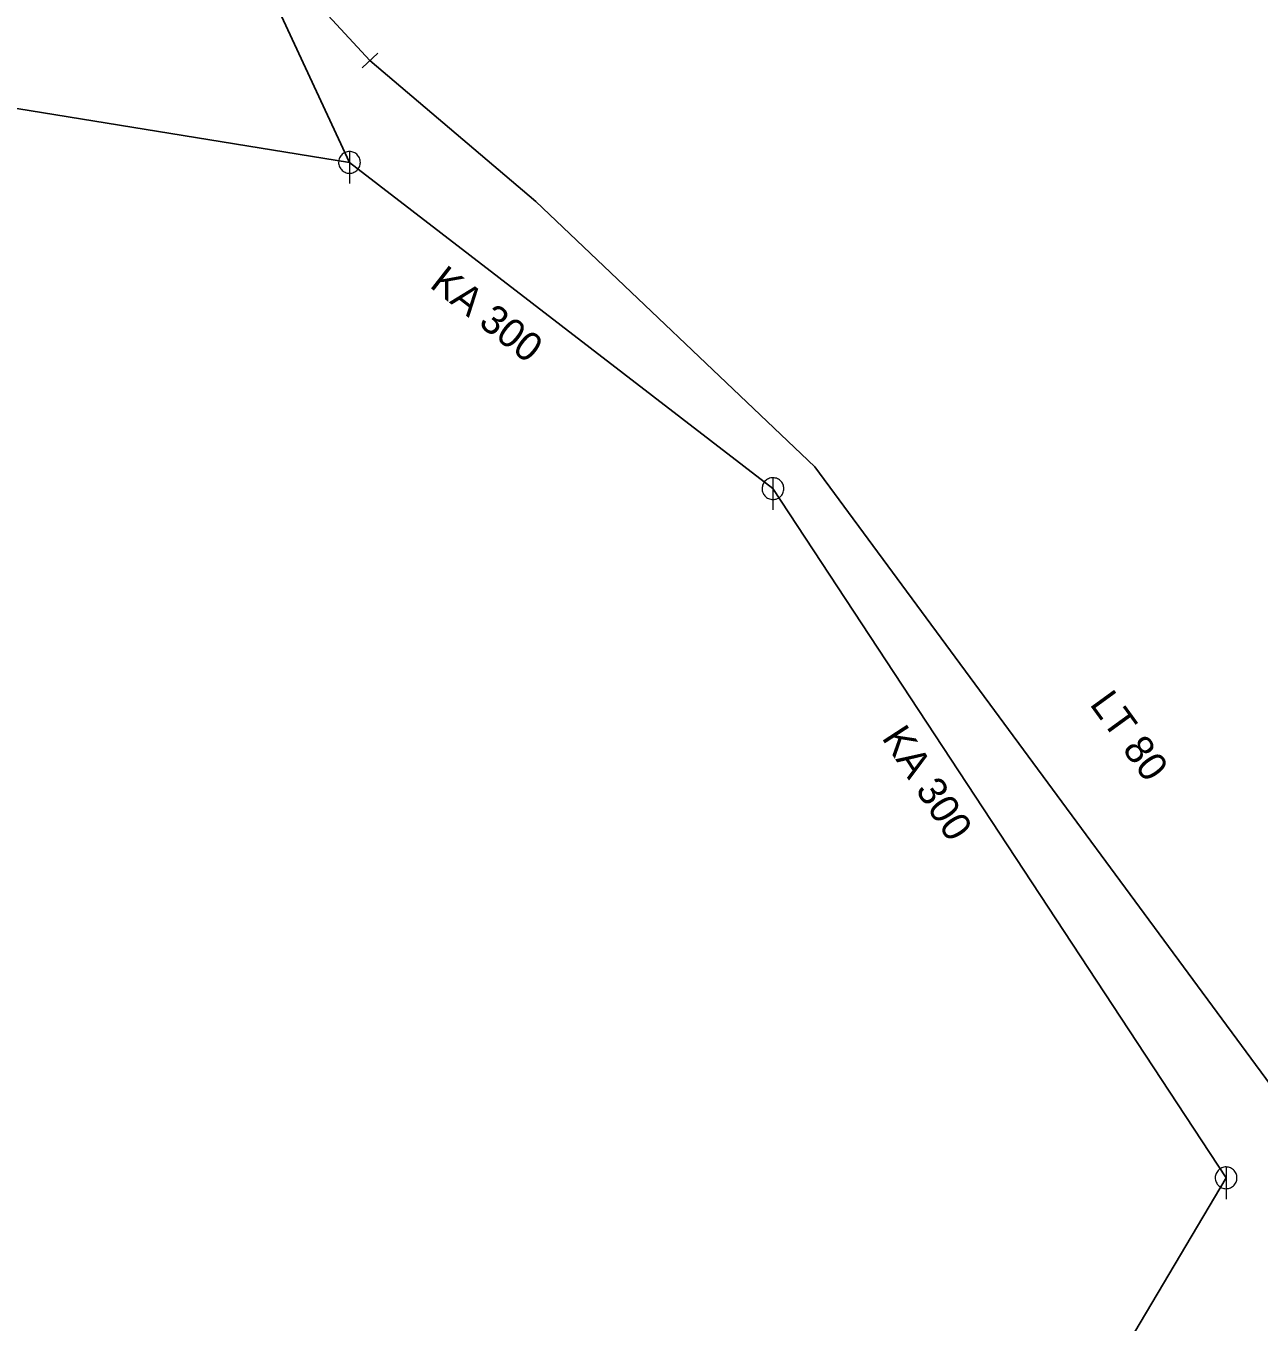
# Model space of a CAD drawing. Extents: x -687515 to -686506, y -974029 to -973461.
# Drawn here: x -687114.54 to -687085.95, y -973866.2 to -973836.14 of the extents above; entities that cross this region are included whole.
import ezdxf
from ezdxf.enums import TextEntityAlignment as Align

# ---------------------------------------------------------------- set-up
doc = ezdxf.new("R2010")
doc.units = 0
doc.header["$LTSCALE"] = 0.27
for name, color, linetype, lineweight in [('1', 7, 'Continuous', 13), ('14', 7, 'Continuous', 25), ('17', 7, 'Continuous', 25), ('22', 7, 'Continuous', 13), ('34', 7, 'Continuous', 13)]:
    doc.layers.add(name, color=color, linetype=linetype, lineweight=lineweight)

msp = doc.modelspace()

# ---------------------------------------------------------------- linework, layer by layer
at = {"layer": '14', "lineweight": 13}
msp.add_line((-687106.566, -973836.941), (-687112.499, -973830.523), dxfattribs=at)
at = {"layer": '14'}
for p, q in [((-687111.064, -973830.634), (-687107.04, -973839.305)), ((-687107.04, -973839.305), (-687097.219, -973846.87)), ((-687097.219, -973846.87), (-687086.71, -973862.85)), ((-687086.71, -973862.85), (-687098.575, -973882.82))]:
    msp.add_line(p, q, dxfattribs=at)
msp.add_lwpolyline([(-687155.19, -973818.55), (-687143.21, -973829.559), (-687133.43, -973835.02), (-687107.04, -973839.305)], dxfattribs=at)
at = {"layer": '17'}
msp.add_lwpolyline([(-687106.566, -973836.941), (-687102.715, -973840.21), (-687096.25, -973846.366), (-687083.209, -973864.046)], dxfattribs=at)
at = {"layer": '22'}
for p, q in [((-687107.039, -973839.053), (-687107.04, -973839.797)), ((-687097.218, -973846.618), (-687097.219, -973847.362)), ((-687086.709, -973862.598), (-687086.71, -973863.342))]:
    msp.add_line(p, q, dxfattribs=at)
for points in [[(-687106.788, -973839.305), (-687106.789, -973839.279), (-687106.793, -973839.253), (-687106.799, -973839.227), (-687106.809, -973839.203), (-687106.821, -973839.179), (-687106.835, -973839.157), (-687106.852, -973839.136), (-687106.87, -973839.118), (-687106.891, -973839.101), (-687106.913, -973839.087), (-687106.937, -973839.075), (-687106.961, -973839.065), (-687106.987, -973839.059), (-687107.013, -973839.055), (-687107.039, -973839.053), (-687107.065, -973839.054), (-687107.091, -973839.058), (-687107.117, -973839.064), (-687107.142, -973839.074), (-687107.165, -973839.086), (-687107.187, -973839.1), (-687107.208, -973839.117), (-687107.226, -973839.135), (-687107.243, -973839.156), (-687107.257, -973839.178), (-687107.269, -973839.202), (-687107.279, -973839.226), (-687107.286, -973839.252), (-687107.29, -973839.278), (-687107.292, -973839.304), (-687107.291, -973839.33), (-687107.287, -973839.356), (-687107.28, -973839.382), (-687107.27, -973839.407), (-687107.258, -973839.43), (-687107.244, -973839.452), (-687107.227, -973839.473), (-687107.209, -973839.491), (-687107.188, -973839.508), (-687107.166, -973839.522), (-687107.143, -973839.534), (-687107.118, -973839.544), (-687107.092, -973839.551), (-687107.066, -973839.555), (-687107.04, -973839.557), (-687107.014, -973839.556), (-687106.988, -973839.552), (-687106.962, -973839.545), (-687106.938, -973839.535), (-687106.914, -973839.523), (-687106.892, -973839.509), (-687106.871, -973839.492), (-687106.853, -973839.474), (-687106.836, -973839.453), (-687106.822, -973839.431), (-687106.81, -973839.408), (-687106.8, -973839.383), (-687106.794, -973839.357), (-687106.79, -973839.331)], [(-687096.967, -973846.87), (-687096.968, -973846.844), (-687096.972, -973846.818), (-687096.978, -973846.792), (-687096.988, -973846.768), (-687097, -973846.744), (-687097.014, -973846.722), (-687097.031, -973846.701), (-687097.049, -973846.683), (-687097.07, -973846.666), (-687097.092, -973846.652), (-687097.116, -973846.64), (-687097.14, -973846.63), (-687097.166, -973846.624), (-687097.192, -973846.62), (-687097.218, -973846.618), (-687097.244, -973846.619), (-687097.27, -973846.623), (-687097.296, -973846.629), (-687097.321, -973846.639), (-687097.344, -973846.651), (-687097.366, -973846.665), (-687097.387, -973846.682), (-687097.405, -973846.7), (-687097.422, -973846.721), (-687097.436, -973846.743), (-687097.448, -973846.767), (-687097.458, -973846.791), (-687097.465, -973846.817), (-687097.469, -973846.843), (-687097.471, -973846.869), (-687097.47, -973846.895), (-687097.466, -973846.921), (-687097.459, -973846.947), (-687097.449, -973846.972), (-687097.437, -973846.995), (-687097.423, -973847.017), (-687097.406, -973847.038), (-687097.388, -973847.056), (-687097.367, -973847.073), (-687097.345, -973847.087), (-687097.322, -973847.099), (-687097.297, -973847.109), (-687097.271, -973847.116), (-687097.245, -973847.12), (-687097.219, -973847.122), (-687097.193, -973847.121), (-687097.167, -973847.117), (-687097.141, -973847.11), (-687097.117, -973847.1), (-687097.093, -973847.088), (-687097.071, -973847.074), (-687097.05, -973847.057), (-687097.032, -973847.039), (-687097.015, -973847.018), (-687097.001, -973846.996), (-687096.989, -973846.973), (-687096.979, -973846.948), (-687096.973, -973846.922), (-687096.969, -973846.896)], [(-687086.458, -973862.85), (-687086.459, -973862.824), (-687086.463, -973862.798), (-687086.469, -973862.772), (-687086.479, -973862.748), (-687086.491, -973862.724), (-687086.505, -973862.702), (-687086.522, -973862.681), (-687086.54, -973862.663), (-687086.561, -973862.646), (-687086.583, -973862.632), (-687086.607, -973862.62), (-687086.631, -973862.61), (-687086.657, -973862.604), (-687086.683, -973862.6), (-687086.709, -973862.598), (-687086.735, -973862.599), (-687086.761, -973862.603), (-687086.787, -973862.609), (-687086.812, -973862.619), (-687086.835, -973862.631), (-687086.857, -973862.645), (-687086.878, -973862.662), (-687086.896, -973862.68), (-687086.913, -973862.701), (-687086.927, -973862.723), (-687086.939, -973862.747), (-687086.949, -973862.771), (-687086.956, -973862.797), (-687086.96, -973862.823), (-687086.962, -973862.849), (-687086.961, -973862.875), (-687086.957, -973862.901), (-687086.95, -973862.927), (-687086.94, -973862.952), (-687086.928, -973862.975), (-687086.914, -973862.997), (-687086.897, -973863.018), (-687086.879, -973863.036), (-687086.858, -973863.053), (-687086.836, -973863.067), (-687086.813, -973863.079), (-687086.788, -973863.089), (-687086.762, -973863.096), (-687086.736, -973863.1), (-687086.71, -973863.102), (-687086.684, -973863.101), (-687086.658, -973863.097), (-687086.632, -973863.09), (-687086.608, -973863.08), (-687086.584, -973863.068), (-687086.562, -973863.054), (-687086.541, -973863.037), (-687086.523, -973863.019), (-687086.506, -973862.998), (-687086.492, -973862.976), (-687086.48, -973862.953), (-687086.47, -973862.928), (-687086.464, -973862.902), (-687086.46, -973862.876)]]:
    msp.add_lwpolyline(points, close=True, dxfattribs=at)
at = {"layer": '34'}
msp.add_line((-687106.745, -973837.112), (-687106.386, -973836.769), dxfattribs=at)

# ---------------------------------------------------------------- texts
at = {"layer": '1'}
for s, rotation, p in [('KA 300', 322, (-687104.054, -973843.082)), ('LT 80 ', 306, (-687089.147, -973852.89)), ('KA 300', 303, (-687093.914, -973853.872))]:
    msp.add_text(s, height=0.6667, rotation=rotation, dxfattribs=at).set_placement(p, align=Align.CENTER)

doc.saveas('drawing.dxf')
